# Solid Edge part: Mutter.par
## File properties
Sűrűség: 0,000 kg/m^3
Pontosság: 0,990
Author: ahadarics
Last saved by: psaghy
Revision: 77
Username: ahadarics
Dokumentum tartalom típus: 0
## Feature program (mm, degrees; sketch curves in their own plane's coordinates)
base feature "unnamed BaseFeature 1"
sketch for "Furat_1" plane through (8, 0, 0) normal (1, 0, 0) x-axis (0, 1, 0)
  hole centre (0, 0) bore radius 7.188
hole "Furat_1" through  StartChamferOffset = 0.47 mm; StartChamferAngle = 45 deg
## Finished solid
Body 1: solid body, 23 faces, 47 edges, 26 vertices.
  Faces by surface: cone 14, plane 8, cylinder 1
  Edges by curve: spline 24, circle 16, line 7
Bounding box of the edges (mm): 8.000 x 27.713 x 24.000, from (0, -13.8564, -12) to (8, 13.8564, 12).
Cylindrical faces by radius (mm): R7.188 x1
Conical faces (half-angle, radius in mm at the cone's reference point): 45 deg R7.658 x1, 60 deg R7.5939 x1, 60 deg R12.9282 x12
Planar faces by outward normal: +x 1, +z 1, -x 1, -z 1, oblique 4
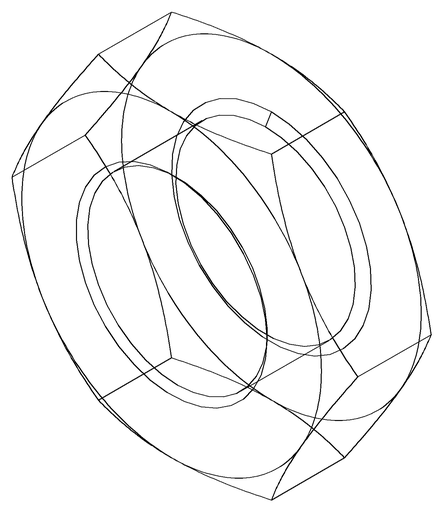
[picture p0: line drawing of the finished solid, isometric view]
